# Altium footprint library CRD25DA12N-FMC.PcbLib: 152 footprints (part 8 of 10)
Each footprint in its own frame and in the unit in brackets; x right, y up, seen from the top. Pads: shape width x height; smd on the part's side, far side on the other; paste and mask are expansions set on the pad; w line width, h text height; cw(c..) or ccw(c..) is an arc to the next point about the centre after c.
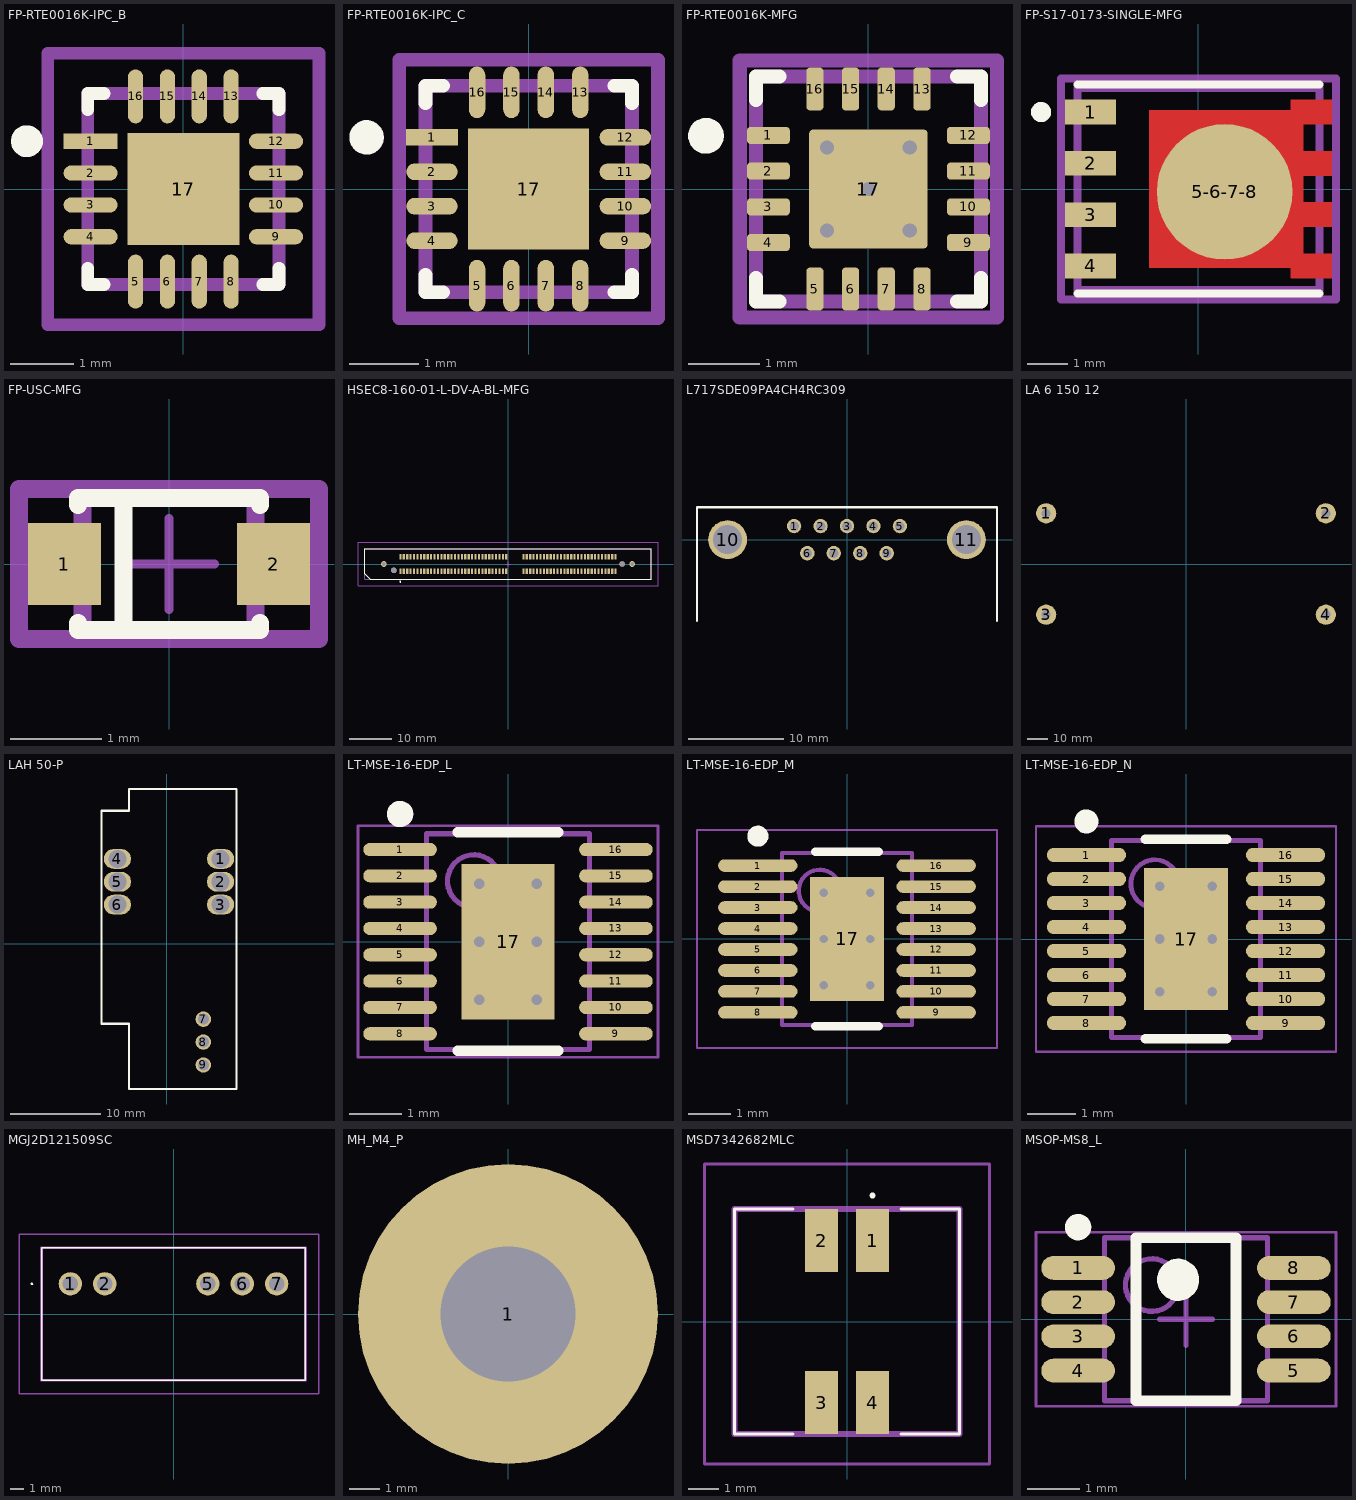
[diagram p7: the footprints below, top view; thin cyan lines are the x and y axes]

## FP-RTE0016K-IPC_B [mm]
pads (17):
  rect 0.849x0.239 smd paste+0 mask+0: 1(-1.455,0.75)
  rrect100% 0.849x0.239 smd paste+0 mask+0: 2(-1.455,0.25) 3(-1.455,-0.25) 4(-1.455,-0.75) 9(1.455,-0.75) 10(1.455,-0.25) 11(1.455,0.25) 12(1.455,0.75)
  rrect100% 0.239x0.849 smd paste+0 mask+0: 5(-0.75,-1.455) 6(-0.25,-1.455) 7(0.25,-1.455) 8(0.75,-1.455) 13(0.75,1.455) 14(0.25,1.455) 15(-0.25,1.455) 16(-0.75,1.455)
  rect 1.76x1.76 smd paste-1000 mask+0: 17(0,0)
Top Overlay:
  circle w0.25: c-2.454,0.75 r0.125
  lines w0.2: -1.5,-1.245 -1.5,-1.5 -1.245,-1.5 ; -1.5,1.245 -1.5,1.5 -1.245,1.5 ; 1.245,-1.5 1.5,-1.5 1.5,-1.245 ; 1.245,1.5 1.5,1.5 1.5,1.245
Top Paste:
  rectangle: -0.557,-0.557 0.557,0.557
Mechanical 5:
  lines w0.2: -2.129,-2.129 2.129,-2.129 2.129,2.129 -2.129,2.129 -2.129,-2.129
  text ".Designator" at 0,0.188 h1
Mechanical 13:
  lines w0.2: -1.5,-1.5 1.5,-1.5 1.5,1.5 -1.5,1.5 -1.5,-1.5
Mechanical 15:
  lines w0.2: -2.129,-2.129 2.129,-2.129 2.129,2.129 -2.129,2.129 -2.129,-2.129
Mechanical 16:
  lines w0.1: -0.5,0 0.5,0 ; 0,-0.5 0,0.5
3D body "IC_Texas_Instruments_LM51571QRTERQ1_eec.STEP": height 0.25, standoff 0, extent -2.129,-2.129 2.129,2.129

## FP-RTE0016K-IPC_C [mm]
pads (17):
  rect 0.749x0.239 smd paste+0 mask+0: 1(-1.405,0.75)
  rrect100% 0.749x0.239 smd paste+0 mask+0: 2(-1.405,0.25) 3(-1.405,-0.25) 4(-1.405,-0.75) 9(1.405,-0.75) 10(1.405,-0.25) 11(1.405,0.25) 12(1.405,0.75)
  rrect100% 0.239x0.749 smd paste+0 mask+0: 5(-0.75,-1.405) 6(-0.25,-1.405) 7(0.25,-1.405) 8(0.75,-1.405) 13(0.75,1.405) 14(0.25,1.405) 15(-0.25,1.405) 16(-0.75,1.405)
  rect 1.76x1.76 smd paste-1000 mask+0: 17(0,0)
Top Overlay:
  circle w0.25: c-2.354,0.75 r0.125
  lines w0.2: -1.5,-1.245 -1.5,-1.5 -1.245,-1.5 ; -1.5,1.245 -1.5,1.5 -1.245,1.5 ; 1.245,-1.5 1.5,-1.5 1.5,-1.245 ; 1.245,1.5 1.5,1.5 1.5,1.245
Top Paste:
  rectangle: -0.557,-0.557 0.557,0.557
Mechanical 5:
  lines w0.2: -1.879,-1.879 1.879,-1.879 1.879,1.879 -1.879,1.879 -1.879,-1.879
  text ".Designator" at 0,0.188 h1
Mechanical 13:
  lines w0.2: -1.5,-1.5 1.5,-1.5 1.5,1.5 -1.5,1.5 -1.5,-1.5
Mechanical 15:
  lines w0.2: -1.879,-1.879 1.879,-1.879 1.879,1.879 -1.879,1.879 -1.879,-1.879
Mechanical 16:
  lines w0.1: -0.5,0 0.5,0 ; 0,-0.5 0,0.5
3D body "IC_Texas_Instruments_LM51571QRTERQ1_eec.STEP": height 0.25, standoff 0, extent -1.879,-1.879 1.879,1.879

## FP-RTE0016K-MFG [mm]
pads (17):
  rrect42% 0.6x0.24 smd paste+0 mask+0: 1(-1.4,0.75) 2(-1.4,0.25) 3(-1.4,-0.25) 4(-1.4,-0.75) 9(1.4,-0.75) 10(1.4,-0.25) 11(1.4,0.25) 12(1.4,0.75)
  rrect42% 0.24x0.6 smd paste+0 mask+0: 5(-0.75,-1.4) 6(-0.25,-1.4) 7(0.25,-1.4) 8(0.75,-1.4) 13(0.75,1.4) 14(0.25,1.4) 15(-0.25,1.4) 16(-0.75,1.4)
  rrect6% 1.66x1.66 smd paste-1000 mask+0: 17(0,0)
via -0.58,0.58 diameter 0.5 hole 0.2
via 0.58,0.58 diameter 0.5 hole 0.2
via 0.58,-0.58 diameter 0.5 hole 0.2
via -0.58,-0.58 diameter 0.5 hole 0.2
via 0,0 diameter 0.5 hole 0.2
Top Overlay:
  circle w0.25: c-2.275,0.745 r0.125
  lines w0.2: -1.575,-1.245 -1.575,-1.575 -1.245,-1.575 ; -1.575,1.245 -1.575,1.575 -1.245,1.575 ; 1.245,-1.575 1.575,-1.575 1.575,-1.245 ; 1.245,1.575 1.575,1.575 1.575,1.245
Top Paste:
  region: -0.705,0.755 0.705,0.755 0.715,0.755 0.733,0.747 0.747,0.733 0.755,0.715 0.755,0.705 0.755,-0.705 0.755,-0.715 0.747,-0.733 0.733,-0.747 0.715,-0.755 0.705,-0.755 -0.705,-0.755 -0.715,-0.755 -0.733,-0.747 -0.747,-0.733 -0.755,-0.715 -0.755,-0.705 -0.755,0.705 -0.755,0.715 -0.747,0.733 -0.733,0.747 -0.715,0.755
Mechanical 5:
  lines w0.2: -1.8,-1.8 1.8,-1.8 1.8,1.8 -1.8,1.8 -1.8,-1.8
  text ".Designator" at 0,0.188 h1
Mechanical 13:
  lines w0.2: -1.575,-1.575 1.575,-1.575 1.575,1.575 -1.575,1.575 -1.575,-1.575
Mechanical 15:
  lines w0.2: -1.8,-1.8 1.8,-1.8 1.8,1.8 -1.8,1.8 -1.8,-1.8
Mechanical 16:
  lines w0.1: -0.5,0 0.5,0 ; 0,-0.5 0,0.5
3D body "IC_Texas_Instruments_XLM51571QRTERQ1_eec.STEP": height 0.25, standoff 0, extent -1.8,-1.8 1.8,1.8

## FP-S17-0173-SINGLE-MFG [mm]
pads (5):
  rect 1.27x0.61 smd paste+0 mask+0: 1(-2.67,1.905) 2(-2.67,0.635) 3(-2.67,-0.635) 4(-2.67,-1.905)
  round 3.356 smd paste+0 mask+0: 5-6-7-8(0.65,-0.069)
Top Layer:
  region: -1.215,1.955 2.285,1.955 2.285,2.21 3.305,2.21 3.305,1.6 2.595,1.6 2.595,0.94 3.305,0.94 3.305,0.33 2.595,0.33 2.595,-0.33 3.305,-0.33 3.305,-0.94 2.595,-0.94 2.595,-1.6 3.305,-1.6 3.305,-2.21 2.285,-2.21 2.285,-1.955 -1.215,-1.955
Top Overlay:
  circle w0.25: c-3.895,1.905 r0.125
  lines w0.2: -2.995,-2.585 2.995,-2.585 ; -2.995,2.585 2.995,2.585
Mechanical 5:
  lines w0.2: -3.405,-2.73 3.405,-2.73 3.405,2.73 -3.405,2.73 -3.405,-2.73
  text ".Designator" at 0,0.188 h1
Mechanical 13:
  lines w0.2: -2.995,-2.5 2.995,-2.5 2.995,2.5 -2.995,2.5 -2.995,-2.5
Mechanical 15:
  lines w0.2: -3.405,-2.73 3.405,-2.73 3.405,2.73 -3.405,2.73 -3.405,-2.73
Mechanical 16:
  lines w0.1: -0.5,0 0.5,0 ; 0,-0.5 0,0.5
3D body "Trans_Vishay_SI7461DP-T1-E3_eec.STEP": height 0.25, standoff 0, extent -3.405,-2.73 3.405,2.73

## FP-USC-MFG [mm]
pads (2):
  rect 0.8x0.9 smd paste+0 mask+0: 1(-1.15,0) 2(1.15,0)
Top Overlay:
  lines w0.2: -1,-0.65 -1,-0.725 1,-0.725 1,-0.65 ; -1,0.65 -1,0.725 1,0.725 1,0.65 ; -0.5,-0.725 -0.5,0.725
Mechanical 5:
  lines w0.2: -1.65,-0.825 -1.65,0.825 1.65,0.825 1.65,-0.825 -1.65,-0.825
  text ".Designator" at 0,0 h1
Mechanical 13:
  lines w0.2: -0.95,-0.725 -0.95,0.725 0.95,0.725 0.95,-0.725 -0.95,-0.725
Mechanical 15:
  lines w0.2: -1.65,-0.825 -1.65,0.825 1.65,0.825 1.65,-0.825 -1.65,-0.825
Mechanical 16:
  lines w0.1: -0.5,0 0.5,0 ; 0,-0.5 0,0.5
3D body "Diode_Toshiba_CUS520_H3F_eec.STEP": height 0.25, standoff 0, extent -1.65,-0.825 1.65,0.825

## HSEC8-160-01-L-DV-A-BL-MFG [mm]
pads (124):
  rect 0.5x1.2 smd paste+0 mask+0: 1(-25.2,-1.7) 2(-25.2,1.7) 3(-24.4,-1.7) 4(-24.4,1.7) 5(-23.6,-1.7) 6(-23.6,1.7) 7(-22.8,-1.7) 8(-22.8,1.7) 9(-22,-1.7) 10(-22,1.7) 11(-21.2,-1.7) 12(-21.2,1.7) 13(-20.4,-1.7) 14(-20.4,1.7) 15(-19.6,-1.7) 16(-19.6,1.7) 17(-18.8,-1.7) 18(-18.8,1.7) 19(-18,-1.7) 20(-18,1.7) 21(-17.2,-1.7) 22(-17.2,1.7) 23(-16.4,-1.7) 24(-16.4,1.7) 25(-15.6,-1.7) 26(-15.6,1.7) 27(-14.8,-1.7) 28(-14.8,1.7) 29(-14,-1.7) 30(-14,1.7) 31(-13.2,-1.7) 32(-13.2,1.7) 33(-12.4,-1.7) 34(-12.4,1.7) 35(-11.6,-1.7) 36(-11.6,1.7) 37(-10.8,-1.7) 38(-10.8,1.7) 39(-10,-1.7) 40(-10,1.7) 41(-9.2,-1.7) 42(-9.2,1.7) 43(-8.4,-1.7) 44(-8.4,1.7) 45(-7.6,-1.7) 46(-7.6,1.7) 47(-6.8,-1.7) 48(-6.8,1.7) 49(-6,-1.7) 50(-6,1.7) 51(-5.2,-1.7) 52(-5.2,1.7) 53(-4.4,-1.7) 54(-4.4,1.7) 55(-3.6,-1.7) 56(-3.6,1.7) 57(-2.8,-1.7) 58(-2.8,1.7) 59(-2,-1.7) 60(-2,1.7) 61(-1.2,-1.7) 62(-1.2,1.7) 63(-0.4,-1.7) 64(-0.4,1.7) 65(3.6,-1.7) 66(3.6,1.7) 67(4.4,-1.7) 68(4.4,1.7) 69(5.2,-1.7) 70(5.2,1.7) 71(6,-1.7) 72(6,1.7) 73(6.8,-1.7) 74(6.8,1.7) 75(7.6,-1.7) 76(7.6,1.7) 77(8.4,-1.7) 78(8.4,1.7) 79(9.2,-1.7) 80(9.2,1.7) 81(10,-1.7) 82(10,1.7) 83(10.8,-1.7) 84(10.8,1.7) 85(11.6,-1.7) 86(11.6,1.7) 87(12.4,-1.7) 88(12.4,1.7) 89(13.2,-1.7) 90(13.2,1.7) 91(14,-1.7) 92(14,1.7) 93(14.8,-1.7) 94(14.8,1.7) 95(15.6,-1.7) 96(15.6,1.7) 97(16.4,-1.7) 98(16.4,1.7) 99(17.2,-1.7) 100(17.2,1.7) 101(18,-1.7) 102(18,1.7) 103(18.8,-1.7) 104(18.8,1.7) 105(19.6,-1.7) 106(19.6,1.7) 107(20.4,-1.7) 108(20.4,1.7) 109(21.2,-1.7) 110(21.2,1.7) 111(22,-1.7) 112(22,1.7) 113(22.8,-1.7) 114(22.8,1.7) 115(23.6,-1.7) 116(23.6,1.7) 117(24.4,-1.7) 118(24.4,1.7) 119(25.2,-1.7) 120(25.2,1.7)
  round 1.34 hole 0.84 paste-2539.97 mask+0: 121(-29.05,0) 122(29.05,0)
  round 1.27 hole 1.27 unplated paste-2539.97 mask+0: ""(-26.7,-1.5) ""(26.7,0)
Top Overlay:
  circle w0.25: c-25.2,-4.125 r0.125
  lines w0.2: -33.55,-2.295 -32.28,-3.565 33.55,-3.565 33.55,3.565 -33.55,3.565 -33.55,-2.295
Top Paste:
  circle w1.27: c29.05,0 r0.635
  circle w1.27: c-29.05,0 r0.635
Mechanical 5:
  lines w0.2: -35.115,-5.09 -35.115,5.09 35.115,5.09 35.115,-5.09 -35.115,-5.09
  text ".Designator" at 0,0.188 h1
Mechanical 13:
  lines w0.2: -33.55,-3.565 -33.55,3.565 33.55,3.565 33.55,-3.565 -33.55,-3.565
Mechanical 15:
  lines w0.2: -35.115,-5.09 -35.115,5.09 35.115,5.09 35.115,-5.09 -35.115,-5.09
Mechanical 16:
  lines w0.1: -0.5,0 0.5,0 ; 0,-0.5 0,0.5
3D body "Conn_Samtec_HSEC8-160-01-L-DV-A-BL_eec.STEP": height 0.25, standoff 0, extent -35.115,-5.09 35.115,5.09

## L717SDE09PA4CH4RC309 [mm] "CONN D-SUB PLUG 9POS R/A SLDR"
height 12.55
pads (11):
  round 1.508 hole 1: 1(-5.54,1.42) 2(-2.77,1.42) 3(0,1.42) 4(2.77,1.42) 5(5.54,1.42) 6(-4.155,-1.42) 7(-1.385,-1.42) 8(1.385,-1.42) 9(4.155,-1.42)
  round 4.066 hole 3.05: 10(-12.495,0) 11(12.495,0)
Top Overlay:
  lines w0.254: -15.7,-8.5 -15.7,3.4 15.7,3.4 15.7,-8.5
3D body "Amphenol L717SDE09PA4CH4RC309 Color.STEP": height 12.55, standoff -3.2, extent -15.4,-15.6 15.405,3

## LA 6 150 12 [mm]
pads (4):
  round 10 hole 4.5: 1(-69,25) 2(69,25) 3(-69,-25) 4(69,-25)
3D body "Fischer Elektronik LA 6 150 + Fan.STEP": height 86.05, standoff 0.05, extent -104.53,-31.052 74.97,30.948

## LAH 50-P [mil]
pads (9):
  oval 118.74x86.61 hole 78.74 mask+7.87: 1(235,370) 2(235,270) 3(235,170) 5(-215,270) 6(-215,170)
  oval 118.74x86.61 hole 78.74 paste-99999 mask+7.87: 4(-215,370)
  round 67.24 hole 47.24: 7(160,-330) 8(160,-430) 9(160,-530)
Top Overlay:
  lines w10: -285,-350 -285,580 -165,580 -165,675 305,675 305,-635 -165,-635 -165,-350 -285,-350
3D body "LAH 50-P_blackbox.stp": height 789.5, standoff -182.94, extent -284.07,-636.02 304.07,675

## LT-MSE-16-EDP_L [mm] "SOP, 16-Leads, Body 4.1x3.1mm, Pitch 0.5mm, Thermal Pad 2.95x1.76mm, IPC High Density"
height 1.1
pads (17):
  oval 1.4x0.25 smd: 1(-2.05,1.75) 2(-2.05,1.25) 3(-2.05,0.75) 4(-2.05,0.25) 5(-2.05,-0.25) 6(-2.05,-0.75) 7(-2.05,-1.25) 8(-2.05,-1.75) 9(2.05,-1.75) 10(2.05,-1.25) 11(2.05,-0.75) 12(2.05,-0.25) 13(2.05,0.25) 14(2.05,0.75) 15(2.05,1.25) 16(2.05,1.75)
  rect 1.76x2.95 smd: 17(0,0)
via 0.55,-1.1 diameter 0.5 hole 0.2
via -0.55,-1.1 diameter 0.5 hole 0.2
via 0.55,0 diameter 0.5 hole 0.2
via -0.55,0 diameter 0.5 hole 0.2
via 0.55,1.1 diameter 0.5 hole 0.2
via -0.55,1.1 diameter 0.5 hole 0.2
Top Overlay:
  circle w0.25: c-2.05,2.425 r0.125
  lines w0.2: -0.951,-2.075 0.951,-2.075 ; -0.951,2.075 0.951,2.075
Mechanical 13:
  circle w0.1: c-0.65,1.15 r0.5
  lines w0.1: -1.55,-2.05 1.55,-2.05 1.55,2.05 -1.55,2.05 -1.55,-2.05
Mechanical 15:
  lines w0.05: -2.85,-2.2 2.85,-2.2 2.85,2.2 -2.85,2.2 -2.85,-2.2
  lines w0.1: -0.5,0 0.5,0 ; 0,-0.5 0,0.5
3D body: height 1.1, standoff 0.05, extent -1.55,-2.05 1.55,2.05

## LT-MSE-16-EDP_M [mm] "SOP, 16-Leads, Body 4.1x3.1mm, Pitch 0.5mm, Thermal Pad 2.95x1.76mm, IPC Low Density"
height 1.1
pads (17):
  oval 1.89x0.3 smd: 1(-2.125,1.75) 2(-2.125,1.25) 3(-2.125,0.75) 4(-2.125,0.25) 5(-2.125,-0.25) 6(-2.125,-0.75) 7(-2.125,-1.25) 8(-2.125,-1.75) 9(2.125,-1.75) 10(2.125,-1.25) 11(2.125,-0.75) 12(2.125,-0.25) 13(2.125,0.25) 14(2.125,0.75) 15(2.125,1.25) 16(2.125,1.75)
  rect 1.76x2.95 smd: 17(0,0)
via -0.55,1.1 diameter 0.5 hole 0.2
via 0.55,1.1 diameter 0.5 hole 0.2
via -0.55,0 diameter 0.5 hole 0.2
via 0.55,0 diameter 0.5 hole 0.2
via -0.55,-1.1 diameter 0.5 hole 0.2
via 0.55,-1.1 diameter 0.5 hole 0.2
Top Overlay:
  circle w0.25: c-2.125,2.45 r0.125
  lines w0.2: -0.755,-2.075 0.755,-2.075 ; -0.755,2.075 0.755,2.075
Mechanical 13:
  circle w0.1: c-0.65,1.15 r0.5
  lines w0.1: -1.55,-2.05 1.55,-2.05 1.55,2.05 -1.55,2.05 -1.55,-2.05
Mechanical 15:
  lines w0.05: -3.575,-2.6 3.575,-2.6 3.575,2.6 -3.575,2.6 -3.575,-2.6
  lines w0.1: -0.5,0 0.5,0 ; 0,-0.5 0,0.5
3D body: height 1.1, standoff 0.05, extent -1.55,-2.05 1.55,2.05

## LT-MSE-16-EDP_N [mm] "SOP, 16-Leads, Body 4.1x3.1mm, Pitch 0.5mm, Thermal Pad 2.95x1.76mm, IPC Medium Density"
height 1.1
pads (17):
  oval 1.65x0.3 smd: 1(-2.075,1.75) 2(-2.075,1.25) 3(-2.075,0.75) 4(-2.075,0.25) 5(-2.075,-0.25) 6(-2.075,-0.75) 7(-2.075,-1.25) 8(-2.075,-1.75) 9(2.075,-1.75) 10(2.075,-1.25) 11(2.075,-0.75) 12(2.075,-0.25) 13(2.075,0.25) 14(2.075,0.75) 15(2.075,1.25) 16(2.075,1.75)
  rect 1.76x2.95 smd: 17(0,0)
via -0.55,1.1 diameter 0.5 hole 0.2
via 0.55,1.1 diameter 0.5 hole 0.2
via -0.55,0 diameter 0.5 hole 0.2
via 0.55,0 diameter 0.5 hole 0.2
via -0.55,-1.1 diameter 0.5 hole 0.2
via 0.55,-1.1 diameter 0.5 hole 0.2
Top Overlay:
  circle w0.25: c-2.075,2.45 r0.125
  lines w0.2: -0.851,-2.075 0.851,-2.075 ; -0.851,2.075 0.851,2.075
Mechanical 13:
  circle w0.1: c-0.65,1.15 r0.5
  lines w0.1: -1.55,-2.05 -1.55,2.05 1.55,2.05 1.55,-2.05 -1.55,-2.05
Mechanical 15:
  lines w0.05: -3.125,-2.35 -3.125,2.35 3.125,2.35 3.125,-2.35 -3.125,-2.35
  lines w0.1: -0.5,0 0.5,0 ; 0,-0.5 0,0.5
3D body: height 1.1, standoff 0.05, extent -1.55,-2.05 1.55,2.05

## MGJ2D121509SC [mm]
pads (5):
  round 1.725 hole 1.15: 1(-7.62,2.23) 2(-5.08,2.23) 5(2.54,2.23) 6(5.08,2.23) 7(7.62,2.23)
Top Overlay:
  lines w0.1: -10.52,2.23 cw(c-10.47,2.23) -10.42,2.23 cw(c-10.47,2.23) -10.52,2.23 ; -9.75,-4.9 9.75,-4.9 9.75,4.9 -9.75,4.9 -9.75,-4.9
Top Designator:
  text ".Designator" at 7.283,0.508 h1.52
Mechanical 13:
  lines w0.2: -9.75,-4.9 9.75,-4.9 9.75,4.9 -9.75,4.9 -9.75,-4.9
Mechanical 15:
  lines w0.1: -11.42,-5.9 10.75,-5.9 10.75,5.9 -11.42,5.9 -11.42,-5.9
3D body "MGJ2D121503SC.stp": height 13.09, standoff -3.51, extent -9.9,-5.09 9.6,4.73

## MH_M4_P [mm] "M4 plated mounting hole"
pads (1):
  round 10 hole 4.5: 1(0,0)
3D body "Extended Standoff (102mm).STEP": height -0.4, standoff -102.4, extent -4,-4.619 4,4.619

## MSD7342682MLC [mm]
pads (4):
  rect 1.1x2.1 smd: 1(0.85,2.7) 2(-0.85,2.7) 3(-0.85,-2.7) 4(0.85,-2.7)
Top Overlay:
  lines w0.1: -1.8,-3.75 -3.75,-3.75 -3.75,3.75 -1.8,3.75 ; 1.8,-3.75 3.75,-3.75 3.75,3.75 1.8,3.75 ; 0.8,4.2 cw(c0.85,4.2) 0.9,4.2 cw(c0.85,4.2) 0.8,4.2
Top Designator:
  text ".Designator" at 7.618,0.758 h1.52
Mechanical 13:
  lines w0.2: -3.75,-3.75 3.75,-3.75 3.75,3.75 -3.75,3.75 -3.75,-3.75
Mechanical 15:
  lines w0.1: -4.75,-4.75 4.75,-4.75 4.75,5.25 -4.75,5.25 -4.75,-4.75
3D body "MSD7342-682MLC.stp": height 4.7, standoff 0, extent -3.75,-3.75 3.75,3.75

## MSOP-MS8_L [mm] "TSOP, 8-Leads, Body 3x3mm, Pitch 0.65mm, IPC High Density"
height 1.1
pads (8):
  oval 1.4x0.45 smd: 1(-2.05,0.975) 2(-2.05,0.325) 3(-2.05,-0.325) 4(-2.05,-0.975) 5(2.05,-0.975) 6(2.05,-0.325) 7(2.05,0.325) 8(2.05,0.975)
Top Overlay:
  circle w0.25: c-2.05,1.75 r0.125
  circle w0.4: c-0.15,0.75 r0.2
  lines w0.2: -0.95,-1.55 -0.95,1.55 0.95,1.55 0.95,-1.55 -0.95,-1.55
Mechanical 13:
  circle w0.1: c-0.65,0.65 r0.5
  lines w0.1: -1.55,-1.55 -1.55,1.55 1.55,1.55 1.55,-1.55 -1.55,-1.55
Mechanical 15:
  lines w0.05: -2.85,-1.65 -2.85,1.65 2.85,1.65 2.85,-1.65 -2.85,-1.65
  lines w0.1: -0.5,0 0.5,0 ; 0,-0.5 0,0.5
3D body: height 1.1, standoff 0, extent -1.55,-1.55 1.55,1.55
